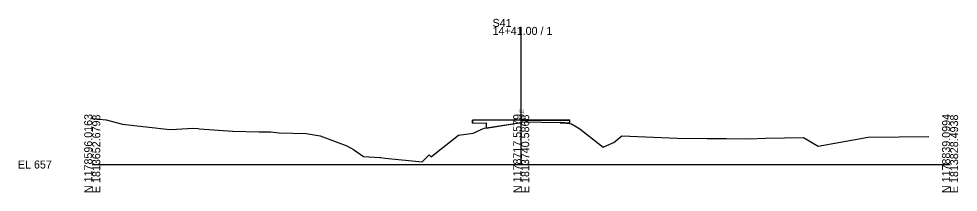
# Model space of a CAD drawing. Extents: x -26 to 8103, y -10 to 6540.
# Drawn here: x 2574.3 to 2902.8, y -9.7 to 51 of the extents above; entities that cross this region are included whole.
import ezdxf

# ---------------------------------------------------------------- set-up
doc = ezdxf.new("R2010")
doc.units = 0
for name, color, linetype in [('Default', 7, 'Continuous'), ('RD_GPK_XS_Cell', 7, 'Continuous'), ('RD_XS_Base', 7, 'Continuous'), ('RD_XS_ExGround', 7, 'Continuous'), ('RD_XS_Misc_Line', 7, 'Continuous'), ('RD_XS_Pave', 7, 'Continuous'), ('RD_XS_TX_Elev_EX', 7, 'Continuous')]:
    doc.layers.add(name, color=color, linetype=linetype)

msp = doc.modelspace()

# ---------------------------------------------------------------- linework, layer by layer
at = {"layer": 'Default'}
for q in [(2733, 15.52), (2767, 15.54)]:
    msp.add_line((2750, 15.53), q, dxfattribs=at)
at = {"layer": 'RD_GPK_XS_Cell'}
for p, q in [((2750, 0), (2750, 48.17)), ((2600, 0), (2750, 0)), ((2750, 0), (2900, 0))]:
    msp.add_line(p, q, dxfattribs=at)
at = {"layer": 'RD_XS_Base'}
for p, q in [((2733, 14.52), (2737.73, 14.62)), ((2737.73, 14.62), (2737.73, 12.78)), ((2763.64, 14.76), (2763.64, 14.54)), ((2763.64, 14.54), (2767, 14.54))]:
    msp.add_line(p, q, dxfattribs=at)
at = {"layer": 'RD_XS_ExGround'}
msp.add_lwpolyline([(2600, 16.06), (2604.81, 15.64), (2610.62, 14.13), (2627.16, 12.25), (2629.43, 12.41), (2635.22, 12.74), (2637.09, 12.59), (2637.45, 12.55), (2649.15, 11.62), (2658.4, 11.49), (2662.49, 11.45), (2665.31, 11.14), (2674.79, 10.91), (2679.68, 10.02), (2689.01, 6.59), (2691.41, 5.26), (2694.89, 2.77), (2700.52, 2.43), (2700.91, 2.42), (2702.44, 2.28), (2715.38, 0.97), (2717.8, 3.45), (2718.52, 2.75), (2721.55, 5.14), (2723.64, 6.79), (2728.04, 10.33), (2733.19, 10.97), (2737.08, 12.68), (2750, 14.7), (2750.56, 14.89), (2763.65, 14.76), (2766.9, 14.33), (2767.57, 14.26), (2770.47, 12.49), (2778.71, 6.12), (2782, 7.6), (2782.43, 7.71), (2785.15, 10.02), (2804.51, 9.28), (2815.06, 9.16), (2821.73, 9.14), (2829.68, 8.95), (2835.48, 9.17), (2848.71, 9.51), (2853.9, 6.43), (2871.32, 9.55), (2882.15, 9.65), (2892.57, 9.79)], dxfattribs=at)
at = {"layer": 'RD_XS_Misc_Line'}
for points in [[(2737.73, 14.62), (2737.73, 12.78), (2750, 14.7), (2750.56, 14.89), (2763.64, 14.76), (2765.32, 14.54), (2767, 14.54), (2767, 15.54), (2750, 15.53), (2733, 15.52), (2733, 14.52)], [(2763.64, 14.76), (2763.64, 14.54), (2765.32, 14.54)]]:
    msp.add_lwpolyline(points, close=True, dxfattribs=at)
at = {"layer": 'RD_XS_Pave'}
for p, q in [((2733, 14.52), (2733, 15.52)), ((2767, 14.54), (2767, 15.54))]:
    msp.add_line(p, q, dxfattribs=at)

# ---------------------------------------------------------------- texts
at = {"layer": 'Default'}
msp.add_text(' 672.53', height=0.8, rotation=90, dxfattribs=at).set_placement((2750.88, 15.53))
at = {"layer": 'RD_GPK_XS_Cell'}
for s, p in [('S41', (2740, 48.17)), ('14+41.00 / 1', (2740, 45.37)), ('EL 657', (2574, -1.4))]:
    msp.add_text(s, height=2.8, dxfattribs=at).set_placement(p)
for s, p in [('N 1178596.0163', (2600, -10)), ('E 1813652.6798', (2602.8, -10)), ('N 1178717.5579', (2750, -10)), ('E 1813740.5868', (2752.8, -10)), ('N 1178839.0994', (2900, -10)), ('E 1813828.4938', (2902.8, -10))]:
    msp.add_text(s, height=2.8, rotation=90, dxfattribs=at).set_placement(p)
at = {"layer": 'RD_XS_TX_Elev_EX'}
msp.add_text('671.70', height=0.8, rotation=90, dxfattribs=at).set_placement((2749.89, 15.85))

doc.saveas('drawing.dxf')
